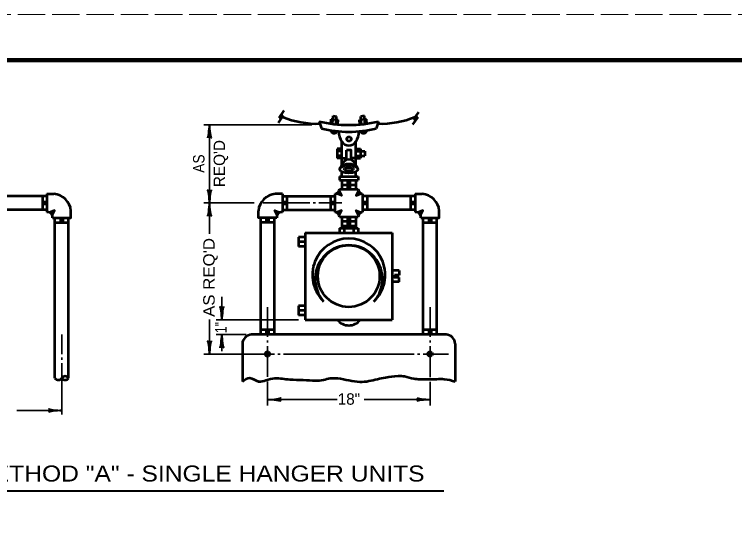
# Model space of a CAD drawing. Extents: x -1 to 679, y 1 to 441.
# Drawn here: x 140.6 to 298.1, y 326.7 to 440.8 of the extents above; entities that cross this region are included whole.
import ezdxf
from ezdxf.enums import TextEntityAlignment as Align

# ---------------------------------------------------------------- set-up
doc = ezdxf.new("R2010")
doc.units = 0
doc.linetypes.add('LONG_DASHED', pattern=[7.5, 6, -1.5])
doc.layers.add('1', color=7, linetype='Continuous', lineweight=35)
doc.layers.add('61', color=7, linetype='Continuous', lineweight=35)

msp = doc.modelspace()

# ---------------------------------------------------------------- linework, layer by layer
at = {"layer": '1', "lineweight": 53}
for p, q in [((198.447, 418.191), (199.594, 419.83)), ((228.942, 419.456), (227.795, 417.818)), ((198.295, 417.092), (199.442, 418.731)), ((198.447, 418.191), (199.442, 418.731)), ((207.206, 417.402), (207.706, 415.902)), ((209.79, 416.922), (209.88, 417.942)), ((209.88, 417.942), (211.366, 417.741)), ((210.166, 416.913), (210.318, 418.657)), ((210.318, 418.657), (211.044, 418.515)), ((210.922, 416.77), (211.044, 418.515)), ((211.297, 416.754), (211.366, 417.741)), ((217.55, 417.906), (216.049, 417.739)), ((216.118, 416.754), (216.049, 417.739)), ((217.124, 418.628), (216.371, 418.513)), ((216.493, 416.767), (216.371, 418.513)), ((217.246, 416.882), (217.124, 418.628)), ((217.619, 416.921), (217.55, 417.906)), ((220.206, 417.402), (219.706, 415.902)), ((228.79, 418.357), (227.643, 416.719)), ((228.79, 418.357), (227.795, 417.818)), ((212.184, 407.699), (212.184, 413.009)), ((215.229, 407.699), (215.229, 413.009)), ((212.184, 411.402), (211.184, 411.402)), ((211.184, 411.402), (211.184, 409.402)), ((213.184, 409.402), (213.184, 411.152)), ((215.229, 411.402), (216.229, 411.402)), ((216.229, 411.402), (216.229, 409.402)), ((212.184, 410.902), (211.184, 410.902)), ((212.184, 409.902), (211.184, 409.902)), ((215.229, 410.902), (217.229, 410.902)), ((215.229, 409.902), (217.229, 409.902)), ((217.229, 410.902), (217.229, 409.902)), ((212.184, 409.402), (211.184, 409.402)), ((212.184, 409.402), (213.184, 409.402)), ((215.229, 409.402), (214.229, 409.402)), ((215.229, 409.402), (216.229, 409.402)), ((212.184, 405.344), (212.184, 406.402)), ((215.229, 405.344), (215.229, 406.402)), ((211.684, 405.344), (215.729, 405.344)), ((211.684, 405.344), (211.684, 404.594)), ((215.729, 405.344), (215.729, 404.594)), ((211.684, 404.594), (215.729, 404.594)), ((212.184, 404.594), (212.184, 402.594)), ((212.184, 403.594), (215.229, 403.594)), ((213.184, 404.094), (214.229, 404.094)), ((215.229, 404.594), (215.229, 402.594)), ((211.684, 402.594), (215.729, 402.594)), ((213.184, 403.094), (214.229, 403.094)), ((147.684, 401.094), (125.684, 401.094)), ((146.684, 401.094), (146.684, 398.094)), ((147.184, 400.094), (147.184, 399.094)), ((147.684, 401.594), (147.684, 397.594)), ((147.684, 401.594), (149.184, 401.594)), ((199.184, 401.594), (197.684, 401.594)), ((199.184, 401.594), (199.184, 397.594)), ((199.184, 401.094), (210.684, 401.094)), ((199.684, 400.094), (199.684, 399.094)), ((200.184, 401.094), (200.184, 398.094)), ((209.684, 401.094), (209.684, 398.094)), ((210.184, 400.094), (210.184, 399.094)), ((210.684, 401.601), (210.684, 397.594)), ((216.731, 401.6), (216.731, 397.588)), ((228.231, 401.094), (216.731, 401.094)), ((217.231, 400.094), (217.231, 399.094)), ((217.731, 401.094), (217.731, 398.094)), ((227.231, 401.094), (227.231, 398.094)), ((227.731, 400.094), (227.731, 399.094)), ((228.231, 401.594), (228.231, 397.594)), ((228.231, 401.594), (229.731, 401.594)), ((147.684, 398.094), (125.684, 398.094)), ((199.184, 398.094), (210.684, 398.094)), ((228.231, 398.094), (216.731, 398.094)), ((149.434, 361.344), (149.434, 396.344)), ((149.434, 395.344), (152.434, 395.344)), ((150.434, 395.844), (151.434, 395.844)), ((152.434, 361.344), (152.434, 396.344)), ((194.434, 370.844), (194.434, 396.344)), ((197.434, 395.344), (194.434, 395.344)), ((196.434, 395.844), (195.434, 395.844)), ((197.434, 370.844), (197.434, 396.344)), ((211.691, 396.594), (215.725, 396.594)), ((212.191, 396.594), (212.191, 394.094)), ((212.191, 395.594), (215.225, 395.594)), ((213.191, 396.094), (214.225, 396.094)), ((215.225, 396.594), (215.225, 394.094)), ((229.981, 370.844), (229.981, 396.344)), ((229.981, 395.344), (232.981, 395.344)), ((230.981, 395.844), (231.981, 395.844)), ((232.981, 370.844), (232.981, 396.344)), ((211.691, 394.094), (215.725, 394.094)), ((211.691, 394.094), (211.691, 393.094)), ((212.191, 394.594), (215.225, 394.594)), ((212.691, 394.094), (212.691, 393.094)), ((213.191, 395.094), (214.225, 395.094)), ((213.191, 394.124), (214.225, 394.124)), ((214.725, 394.094), (214.725, 393.094)), ((215.725, 394.094), (215.725, 393.094)), ((204.191, 393.094), (223.225, 393.094)), ((204.191, 393.094), (204.191, 374.094)), ((223.225, 393.094), (223.225, 374.094)), ((204.191, 392.094), (202.691, 392.094)), ((202.691, 392.094), (202.691, 390.094)), ((204.191, 391.094), (202.691, 391.094)), ((204.191, 390.094), (202.691, 390.094)), ((224.725, 384.844), (223.225, 384.844)), ((224.725, 384.844), (224.725, 383.844)), ((224.725, 383.844), (223.725, 383.844)), ((224.725, 382.344), (224.725, 383.344)), ((224.725, 382.344), (223.225, 382.344)), ((204.191, 377.094), (202.691, 377.094)), ((202.691, 377.094), (202.691, 375.094)), ((204.191, 376.094), (202.691, 376.094)), ((204.191, 375.094), (202.691, 375.094)), ((204.191, 374.094), (223.225, 374.094)), ((197.434, 371.844), (194.434, 371.844)), ((232.981, 371.844), (229.981, 371.844)), ((234.981, 370.844), (192.434, 370.844)), ((196.434, 371.344), (195.434, 371.344)), ((231.981, 371.344), (230.981, 371.344)), ((190.434, 368.844), (190.434, 360.594)), ((236.986, 368.844), (236.986, 360.594))]:
    msp.add_line(p, q, dxfattribs=at)
at = {"layer": '1'}
for p, q in [((205.644, 416.674), (181.976, 416.674)), ((183.235, 399.594), (183.235, 416.674)), ((192.976, 399.594), (181.976, 399.594)), ((183.235, 399.594), (183.235, 392.818)), ((205.184, 399.594), (194.976, 399.594)), ((202.184, 399.594), (201.684, 399.594)), ((206.434, 399.594), (205.934, 399.594)), ((212.184, 399.594), (207.184, 399.594)), ((185.938, 374.094), (185.938, 379.101)), ((195.934, 376.844), (195.934, 370.322)), ((231.486, 376.844), (231.486, 370.322)), ((183.235, 374.114), (183.235, 366.594)), ((202.691, 374.094), (184.708, 374.094)), ((150.938, 370.844), (150.938, 366.594)), ((191.29, 370.839), (184.708, 370.839)), ((185.938, 370.844), (185.938, 367.25)), ((195.934, 369.572), (195.934, 369.072)), ((231.486, 369.572), (231.486, 369.072)), ((195.934, 368.322), (195.934, 361.595)), ((231.486, 368.322), (231.486, 361.539)), ((150.938, 365.844), (150.938, 365.344)), ((181.976, 366.594), (197.436, 366.594)), ((198.199, 366.594), (198.699, 366.594)), ((199.449, 366.594), (227.983, 366.594)), ((228.733, 366.594), (229.233, 366.594)), ((229.985, 366.594), (235.486, 366.594)), ((150.938, 364.594), (150.938, 353.344)), ((195.934, 360.595), (195.934, 355.344)), ((231.486, 360.539), (231.486, 355.344)), ((196.026, 356.62), (211.131, 356.62)), ((217.03, 356.62), (231.486, 356.62)), ((141.1, 354.233), (150.938, 354.233))]:
    msp.add_line(p, q, dxfattribs=at)
at = {"layer": '1', "lineweight": 40}
msp.add_line((92.546, 336.708), (234.457, 336.708), dxfattribs=at)
at = {"layer": '1', "lineweight": 53}
for points in [[(214.229, 409.402), (214.229, 411.152), (213.184, 411.152)], [(211.604, 402.275), (212.089, 401.228), (210.997, 401.676)], [(215.809, 402.275), (215.324, 401.228), (216.415, 401.676)], [(148.86, 396.927), (149.345, 397.974), (148.254, 397.526)], [(148.934, 396.344), (152.934, 396.344), (152.934, 397.844)], [(197.934, 396.344), (193.934, 396.344), (193.934, 397.844)], [(198.007, 396.927), (197.522, 397.974), (198.614, 397.526)], [(211.61, 396.919), (212.095, 397.966), (211.004, 397.518)], [(215.805, 396.913), (215.32, 397.96), (216.411, 397.512)], [(229.408, 396.927), (229.893, 397.974), (228.801, 397.526)], [(229.481, 396.344), (233.481, 396.344), (233.481, 397.844)], [(224.725, 383.344), (223.725, 383.344), (223.725, 383.844)]]:
    msp.add_lwpolyline(points, dxfattribs=at)
for centre, radius in [((213.751, 413.575), 0.5), ((213.697, 383.606), 6.75), ((195.936, 366.595), 0.5), ((231.485, 366.595), 0.5)]:
    msp.add_circle(centre, radius, dxfattribs=at)
for centre, radius, start, end in [((206.723, 436.687), 19.77, 247.65241, 271.85853), ((213.706, 445.193), 28.542, 256.83593, 283.1638), ((220.689, 436.687), 19.77, 268.14138, 292.34759), ((213.706, 439.527), 24.375, 255.74997, 284.25003), ((210.467, 415.665), 0.821, 192.33045, 332.21364), ((216.947, 415.665), 0.821, 207.78636, 347.66955), ((213.706, 407.566), 1.528, 4.98578, 175.01422), ((210.585, 402.699), 1.103, 275.11437, 291.91656), ((210.585, 402.699), 1.103, 291.91656, 354.5292), ((210.585, 402.699), 1.103, 291.91738, 337.37313), ((216.827, 402.699), 1.103, 185.4708, 248.08344), ((216.827, 402.699), 1.103, 202.62687, 248.08262), ((216.827, 402.699), 1.103, 248.08344, 265.0377), ((148.89, 397.55), 4.055, 4.15965, 85.84034), ((197.978, 397.55), 4.055, 94.15966, 175.84035), ((229.437, 397.55), 4.055, 4.15965, 85.84034), ((147.842, 396.502), 1.103, 68.08344, 98.24718), ((147.842, 396.502), 1.103, 351.75282, 68.08344), ((147.842, 396.502), 1.103, 22.62687, 68.08262), ((199.026, 396.502), 1.103, 111.91656, 188.24718), ((199.026, 396.502), 1.103, 111.91738, 157.37313), ((199.026, 396.502), 1.103, 81.75282, 111.91656), ((210.592, 396.495), 1.103, 68.08344, 85.22882), ((210.592, 396.495), 1.103, 5.16652, 68.08344), ((210.592, 396.495), 1.103, 22.62687, 68.08262), ((216.823, 396.489), 1.103, 111.91656, 174.5292), ((216.823, 396.489), 1.103, 111.91738, 157.37313), ((216.823, 396.489), 1.103, 94.77118, 111.91656), ((228.39, 396.502), 1.103, 68.08344, 98.24718), ((228.39, 396.502), 1.103, 351.75282, 68.08344), ((228.39, 396.502), 1.103, 22.62687, 68.08262), ((213.708, 383.869), 7.975, 313.60282, 226.39718), ((213.708, 382.991), 7.364, 318.31863, 221.68137), ((213.708, 376.004), 3.159, 217.18292, 322.81708), ((192.539, 368.739), 2.108, 92.86473, 177.13527), ((234.876, 368.739), 2.108, 2.86473, 87.13527), ((150.184, 361.87), 0.916, 215.00672, 324.99328), ((151.684, 360.818), 0.916, 35.00672, 144.99328), ((151.684, 361.87), 0.916, 215.00672, 324.99328)]:
    msp.add_arc(centre, radius, start, end, dxfattribs=at)
at = {"layer": '1', "lineweight": 40}
for centre, major_axis, ratio, start_param, end_param in [((183.023, 415.554), (0.176, 1.756), 0.07063, 3.1407148, 5.41811), ((183.023, 415.554), (0.176, 1.756), 0.07063, 3.1407148, 5.41811), ((183.511, 415.583), (-0.156, 1.786), 0.122415, 0.8963533, 3.1415927), ((183.511, 415.583), (-0.156, 1.786), 0.122415, 0.8963533, 3.1415927), ((182.959, 400.685), (0.156, -1.786), 0.122415, 0.8963533, 3.1415927), ((182.959, 400.685), (0.156, -1.786), 0.122415, 0.8963533, 3.1415927), ((183.447, 400.715), (-0.176, -1.756), 0.07063, 3.1407148, 5.41811), ((183.447, 400.715), (-0.176, -1.756), 0.07063, 3.1407148, 5.41811), ((183.023, 398.474), (0.176, 1.756), 0.07063, 3.1407148, 5.41811), ((183.023, 398.474), (0.176, 1.756), 0.07063, 3.1407148, 5.41811), ((183.511, 398.503), (-0.156, 1.786), 0.122415, 0.8963533, 3.1415927), ((183.511, 398.503), (-0.156, 1.786), 0.122415, 0.8963533, 3.1415927), ((185.662, 375.185), (0.156, -1.786), 0.122415, 0.8963533, 3.1415927), ((186.149, 375.215), (-0.176, -1.756), 0.07063, 3.1407148, 5.41811), ((185.726, 369.724), (0.176, 1.756), 0.07063, 3.1407148, 5.41811), ((186.214, 369.753), (-0.156, 1.786), 0.122415, 0.8963533, 3.1415927), ((182.959, 367.685), (0.156, -1.786), 0.122415, 0.8963533, 3.1415927), ((182.959, 367.685), (0.156, -1.786), 0.122415, 0.8963533, 3.1415927), ((183.447, 367.715), (-0.176, -1.756), 0.07063, 3.1407148, 5.41811), ((183.447, 367.715), (-0.176, -1.756), 0.07063, 3.1407148, 5.41811), ((197.117, 356.896), (-1.786, -0.156), 0.122415, 0.8963533, 3.1415927), ((197.147, 356.408), (-1.756, 0.176), 0.07063, 3.1407148, 5.41811), ((230.385, 356.351), (1.786, 0.156), 0.122415, 0.8963533, 3.1415927), ((230.356, 356.839), (1.756, -0.176), 0.07063, 3.1407148, 5.41811), ((149.817, 354.445), (1.756, -0.176), 0.07063, 3.1407148, 5.41811), ((149.847, 353.957), (1.786, 0.156), 0.122415, 0.8963533, 3.1415927)]:
    msp.add_ellipse(centre, major_axis=major_axis, ratio=ratio, start_param=start_param, end_param=end_param, dxfattribs=at)
at = {"layer": '1', "lineweight": 53}
for centre, major_axis, ratio, start_param, end_param in [((213.706, 415.402), (0, 3.25), 0.692308, 1.615522, 4.6676498), ((213.706, 406.969), (2, 0), 0.5625, 6.2831853, 9.424778)]:
    msp.add_ellipse(centre, major_axis=major_axis, ratio=ratio, start_param=start_param, end_param=end_param, dxfattribs=at)
for major_axis, ratio in [((2, 0), 0.4375), ((1, 0), 0.375)]:
    msp.add_ellipse((213.706, 406.969), major_axis=major_axis, ratio=ratio, dxfattribs=at)
msp.add_spline([(190.434, 360.594), (192.03, 361.377), (193.984, 360.612), (195.597, 360.867), (197.551, 361.292), (200.778, 361.037), (203.751, 360.952), (206.469, 360.782), (208.167, 360.952), (209.611, 361.292), (211.31, 361.292), (216.151, 360.527), (218.105, 360.697), (219.973, 361.122), (221.757, 361.462), (224.475, 361.802), (225.919, 361.717), (227.957, 361.207), (229.146, 361.122), (231.1, 361.122), (232.968, 361.122), (234.582, 361.122), (236.986, 360.594)], degree=3, dxfattribs=at)
at = {"layer": '61', "linetype": 'LONG_DASHED', "lineweight": 13}
msp.add_line((-1.178, 440.796), (678.842, 440.796), dxfattribs=at)
at = {"layer": '61', "lineweight": 158}
msp.add_lwpolyline([(667.862, 430.796), (28.822, 430.796), (28.822, 10.776)], dxfattribs=at)

# ---------------------------------------------------------------- texts
at = {"layer": '1'}
msp.add_text("REQ'D", height=2.5, rotation=90, dxfattribs=at).set_placement((186.644, 408.199), align=Align.CENTER)
at = {"layer": '1', "width": 0.9}
msp.add_text('AS', height=2.5, rotation=90, dxfattribs=at).set_placement((182.144, 408.199), align=Align.CENTER)
at = {"layer": '1'}
for s, width, p in [("AS REQ'D", 1.1, (184.372, 374.692)), ('1"', 0.8, (186.971, 371.154))]:
    msp.add_text(s, height=2.5, rotation=90, dxfattribs=dict(at, width=width)).set_placement(p)
msp.add_text('18"', height=2.5, dxfattribs=at).set_placement((211.274, 355.51))
at = {"layer": '1', "width": 1.15}
msp.add_text('SUSPENSION METHOD "A" - SINGLE HANGER UNITS', height=3.5, dxfattribs=at).set_placement((94.567, 338.73))

doc.saveas('drawing.dxf')
